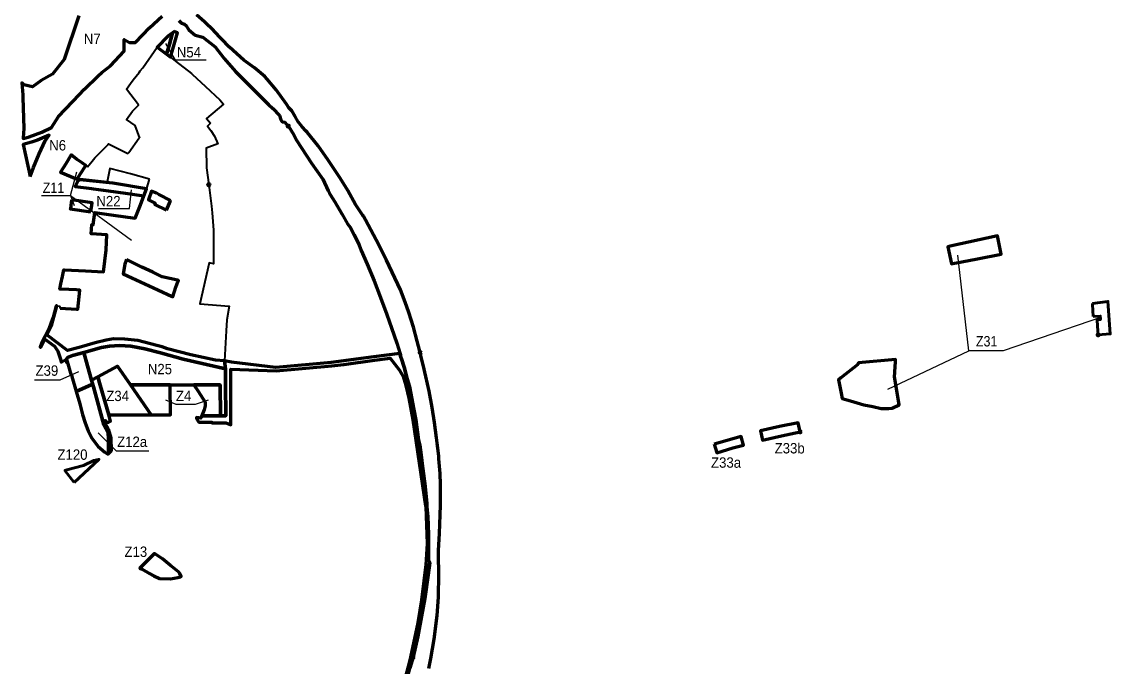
# Model space of a CAD drawing. Extents: x -650277 to -643422, y -1073980 to -1066720.
# Drawn here: x -645938 to -643422, y -1070696 to -1069207 of the extents above; entities that cross this region are included whole.
import ezdxf

# ---------------------------------------------------------------- set-up
doc = ezdxf.new("R2010")
doc.units = 0
doc.header["$LTSCALE"] = 9.6
doc.header["$PDMODE"] = 32
doc.header["$PDSIZE"] = 4.8
for name, color, linetype, lineweight in [('1', 7, 'Continuous', 60), ('11', 7, 'Continuous', 60), ('15', 7, 'Continuous', 60), ('3', 7, 'Continuous', 60), ('40', 7, 'Continuous', 60), ('42', 7, 'Continuous', 60), ('5', 7, 'Continuous', 60), ('60', 7, 'Continuous', 60), ('63', 7, 'Continuous', 25), ('7', 7, 'Continuous', 60), ('8', 7, 'Continuous', 60)]:
    doc.layers.add(name, color=color, linetype=linetype, lineweight=lineweight)

msp = doc.modelspace()

# ---------------------------------------------------------------- linework, layer by layer
at = {"layer": '1', "lineweight": 25}
msp.add_line((-645826, -1069608), (-645685, -1069711), dxfattribs=at)
at = {"layer": '1'}
msp.add_line((-645623.75, -1069825.97), (-645590.964, -1069841.09), dxfattribs=at)
at = {"layer": '1', "lineweight": 40}
msp.add_line((-645726.542, -1069939.398), (-645742.967, -1069941.862), dxfattribs=at)
for points in [[(-645668.722, -1069398.75), (-645696.19, -1069362.01), (-645692.38, -1069356.67), (-645690.81, -1069354.28), (-645687.22, -1069349), (-645680.8, -1069341.08), (-645667, -1069324.06), (-645664.89, -1069320.2), (-645658.9, -1069312.83), (-645625.11, -1069265.42), (-645604.114, -1069281.49), (-645594.94, -1069288.511)], [(-645594.94, -1069288.511), (-645583.13, -1069297.55), (-645546.19, -1069325.81), (-645544.26, -1069327.35), (-645513.41, -1069356.18), (-645480.72, -1069386.96), (-645471.738, -1069397.026), (-645511.464, -1069429.794), (-645501.878, -1069440.838)], [(-645665.58, -1069475.61), (-645675.91, -1069446.56), (-645696.45, -1069432.21), (-645682.28, -1069412.88), (-645678.06, -1069408.54), (-645668.61, -1069398.9), (-645668.722, -1069398.75)], [(-645501.878, -1069440.838), (-645508.994, -1069447.955), (-645501, -1069458), (-645493, -1069471), (-645484.783, -1069488.256), (-645512, -1069499), (-645511, -1069544), (-645506, -1069583)], [(-645786.388, -1069541.673), (-645779.376, -1069532.962), (-645778.754, -1069532.198), (-645769.369, -1069520.672), (-645768.995, -1069520.305), (-645752.715, -1069504.328), (-645738.986, -1069489.868), (-645737.897, -1069488.534), (-645702.82, -1069506.64), (-645692.87, -1069511.229), (-645690.84, -1069508.32), (-645667.31, -1069474.6), (-645665.58, -1069475.61)], [(-645836.44, -1069534.5), (-645824.05, -1069514.34), (-645811.75, -1069523.81), (-645808.1, -1069526.61), (-645799.07, -1069532.8), (-645790.62, -1069538.59), (-645786.388, -1069541.673)], [(-645810.08, -1069570.39), (-645848.78, -1069553.91), (-645836.44, -1069534.5)], [(-645643.16, -1069570.6), (-645687.29, -1069558.04), (-645734.5, -1069545.89), (-645736.8, -1069556.91), (-645741.14, -1069576.19), (-645769.04, -1069573), (-645803.513, -1069569.263), (-645810.08, -1069570.39)], [(-645676.34, -1069660.28), (-645670.23, -1069644.67), (-645664.19, -1069629.24), (-645657.52, -1069612.2), (-645656.15, -1069608.71), (-645649.91, -1069592.39), (-645648.68, -1069589.06), (-645644.56, -1069575.61), (-645643.16, -1069570.6)], [(-645506, -1069583), (-645500.137, -1069632.833), (-645500.137, -1069632.833)], [(-645500.137, -1069632.833), (-645498, -1069648), (-645495, -1069688), (-645495, -1069744), (-645495, -1069766), (-645504.976, -1069763.332), (-645527, -1069858), (-645459.312, -1069864.01), (-645464.288, -1069895.362), (-645465.756, -1069921.035), (-645469.701, -1069990.011)], [(-645839.721, -1069780.247), (-645839.658, -1069779.835), (-645791.2, -1069781.92), (-645749.48, -1069784.61), (-645743.36, -1069733.7), (-645743.01, -1069730.72), (-645741.43, -1069698.68), (-645763.24, -1069697.58), (-645777.62, -1069696.85), (-645776.45, -1069675.26), (-645773.02, -1069675.47), (-645769.36, -1069648), (-645769.264, -1069647.213), (-645726.57, -1069653.22), (-645676.34, -1069660.28)], [(-645804.185, -1069825.84), (-645804.28, -1069826.76), (-645812.18, -1069826.3), (-645847.62, -1069824.26), (-645850.63, -1069824.09), (-645848.35, -1069812.09), (-645844.57, -1069795.07), (-645841.41, -1069779.76), (-645839.658, -1069779.835), (-645839.721, -1069780.247)], [(-645742.967, -1069941.862), (-645768.424, -1069948.431), (-645833, -1069966), (-645880.431, -1069930.3), (-645874.219, -1069917.496), (-645869.262, -1069905.935), (-645863.95, -1069889.468), (-645857.289, -1069863.338), (-645857.204, -1069862.954), (-645850.92, -1069863.41), (-645849.79, -1069868.4), (-645808.84, -1069870.75), (-645808.28, -1069865.39), (-645804.185, -1069825.84)], [(-645469.701, -1069990.011), (-645490.814, -1069988.074), (-645547.4, -1069976.382), (-645614.072, -1069957.797), (-645625.979, -1069954.92), (-645670.325, -1069943.002), (-645699.889, -1069939.714), (-645726.542, -1069939.398)]]:
    msp.add_lwpolyline(points, dxfattribs=at)
at = {"layer": '1'}
for points in [[(-645836.44, -1069534.5), (-645848.78, -1069553.91), (-645810.08, -1069570.39), (-645803.07, -1069558.62), (-645790.62, -1069538.59), (-645799.07, -1069532.8), (-645808.1, -1069526.61), (-645811.75, -1069523.81), (-645824.05, -1069514.34)], [(-645639.638, -1070114.895), (-645594.733, -1070114.868), (-645595.2, -1070045.403), (-645687.31, -1070045.724)], [(-645522.587, -1070116.952), (-645478.664, -1070117.114), (-645479.429, -1070045.409), (-645540.433, -1070045.752), (-645530.3, -1070060.08), (-645514.49, -1070085.4), (-645514.56, -1070090.91), (-645514.61, -1070094.35), (-645517.02, -1070103.08), (-645518.35, -1070106.87), (-645521.73, -1070114.83)], [(-645594.769, -1070494.065), (-645577.47, -1070490.3), (-645571.13, -1070488.89), (-645569.97, -1070488.3), (-645572.86, -1070481.41), (-645575.7, -1070477.77), (-645591.49, -1070465.19), (-645594.62, -1070462.7), (-645612.77, -1070447.82), (-645631.63, -1070435.3), (-645636.42, -1070439.93), (-645648.9, -1070452.38), (-645665.6, -1070469.04), (-645660.29, -1070471.12), (-645643.4, -1070481.02), (-645633.35, -1070486.91), (-645620.22, -1070493)]]:
    msp.add_lwpolyline(points, close=True, dxfattribs=at)
at = {"layer": '1', "lineweight": 25}
for points in [[(-645893, -1069608), (-645826, -1069608), (-645811, -1069553)], [(-643442.122, -1069889.276), (-643669.749, -1069967.17), (-643749.085, -1069967.17)]]:
    msp.add_lwpolyline(points, dxfattribs=at)
at = {"layer": '1'}
for points in [[(-645849.79, -1069868.4), (-645811.848, -1069870.577), (-645808.84, -1069870.75), (-645804.28, -1069826.76), (-645812.18, -1069826.3), (-645847.62, -1069824.26), (-645850.63, -1069824.09), (-645848.35, -1069812.09), (-645844.57, -1069795.07), (-645841.41, -1069779.76), (-645839.658, -1069779.835), (-645791.2, -1069781.92), (-645749.48, -1069784.61), (-645743.36, -1069733.7), (-645741.43, -1069698.68), (-645777.62, -1069696.85), (-645776.45, -1069675.26), (-645773.02, -1069675.47), (-645769.264, -1069647.213), (-645726.57, -1069653.22), (-645676.34, -1069660.28), (-645664.19, -1069629.24), (-645656.15, -1069608.71)], [(-645594.58, -1069619.56), (-645621.56, -1069605.68), (-645626.95, -1069602.91), (-645638.203, -1069597.8), (-645645.715, -1069618.085), (-645629.78, -1069626.03), (-645630.93, -1069628.84), (-645603.7, -1069641.75)], [(-645823.082, -1069618.279), (-645823.13, -1069618.452), (-645825.295, -1069632.053), (-645826.133, -1069638.843), (-645826.151, -1069639.057), (-645778.45, -1069645.92)], [(-645778.45, -1069645.92), (-645775.46, -1069625.13), (-645823.082, -1069618.279)], [(-645603.7, -1069641.75), (-645594.818, -1069620.139), (-645594.58, -1069619.56)], [(-645696.517, -1069756.039), (-645700.028, -1069766.286), (-645704.355, -1069788.786), (-645623.75, -1069825.97)], [(-645578.134, -1069803.73), (-645613.84, -1069795.78), (-645635.79, -1069785.23), (-645660.57, -1069773.31), (-645696.517, -1069756.039)], [(-645590.964, -1069841.09), (-645589.23, -1069841.89), (-645582.31, -1069820.05), (-645577.52, -1069807.26), (-645576.34, -1069804.13), (-645578.134, -1069803.73)], [(-645772.853, -1070049.868), (-645774.423, -1070044.167), (-645783.063, -1070047.855), (-645812.76, -1070060.53)], [(-645812.76, -1070060.53), (-645804.52, -1070089.63), (-645797.66, -1070113.88), (-645791.72, -1070133.09), (-645784.83, -1070151.9), (-645784.83, -1070151.9)], [(-645737.756, -1070204.389), (-645737.624, -1070169.544), (-645738.79, -1070156.281), (-645748.62, -1070137.889), (-645772.853, -1070049.868)], [(-645784.83, -1070151.9), (-645776.26, -1070168.94), (-645761.78, -1070188.29), (-645746.73, -1070201.04), (-645739.12, -1070205.9), (-645737.756, -1070204.389)]]:
    msp.add_lwpolyline(points, dxfattribs=at)
at = {"layer": '1', "lineweight": 53}
for points in [[(-643450.3, -1069929.7), (-643422.204, -1069927.68), (-643427.6, -1069852.59), (-643463.51, -1069857.44)], [(-643463.51, -1069857.44), (-643463.31, -1069860.18), (-643461.327, -1069887.84)], [(-643461.327, -1069887.84), (-643445.37, -1069886.7), (-643444.79, -1069894.68), (-643452.77, -1069895.25), (-643451.74, -1069909.63), (-643450.3, -1069929.7)]]:
    msp.add_lwpolyline(points, dxfattribs=at)
msp.add_lwpolyline([(-645816.9, -1070270.96), (-645760.05, -1070217.79), (-645760.91, -1070217.98), (-645772.08, -1070220.39), (-645795.85, -1070231.81), (-645833.92, -1070241.96), (-645838.53, -1070243.19)], close=True, dxfattribs=at)
at = {"layer": '1'}
for p in [(-645506, -1069583), (-643450.3, -1069929.7)]:
    msp.add_point(p, dxfattribs=at)
at = {"layer": '11'}
msp.add_lwpolyline([(-645639.638, -1070114.895), (-645687.31, -1070045.724), (-645717.36, -1070002.12), (-645762.868, -1070026.606), (-645757.215, -1070045.97), (-645737.075, -1070114.955)], close=True, dxfattribs=at)
at = {"layer": '15'}
for points in [[(-645586.39, -1069229.32), (-645589.844, -1069231.908), (-645597.738, -1069261.522), (-645604.114, -1069281.49), (-645594.94, -1069288.511), (-645587.298, -1069264.578), (-645578.713, -1069232.375)], [(-645735.532, -1069956.306), (-645712.222, -1069954.725), (-645686.147, -1069956.306), (-645654.145, -1069962.232), (-645617.403, -1069971.714), (-645565.133, -1069986.508), (-645467.472, -1070008.38), (-645469.701, -1069990.011), (-645490.814, -1069988.074), (-645547.4, -1069976.382), (-645601.753, -1069962.317), (-645614.072, -1069957.797), (-645625.979, -1069954.92), (-645670.325, -1069943.002), (-645699.889, -1069939.714), (-645726.542, -1069939.398), (-645742.967, -1069941.862), (-645768.424, -1069948.431), (-645806, -1069959), (-645833, -1069966), (-645880.431, -1069930.3), (-645874.219, -1069917.496), (-645869.262, -1069905.935), (-645863.95, -1069889.468), (-645857.289, -1069863.338), (-645857.204, -1069862.954), (-645858.78, -1069862.84), (-645865.78, -1069888.76), (-645870.89, -1069903.5), (-645876.15, -1069916.47), (-645892.09, -1069947.98), (-645895.66, -1069958.42), (-645894.25, -1069958.7), (-645885.422, -1069940.184), (-645862.782, -1069955.809), (-645854.81, -1069967.927), (-645849.1, -1069986.42), (-645847.135, -1069993.337), (-645836.64, -1069987.18), (-645834.65, -1069994.21), (-645833.32, -1069991.86), (-645835, -1069985), (-645833, -1069982), (-645821, -1069978), (-645794.679, -1069970.596), (-645753.706, -1069959.071)]]:
    msp.add_lwpolyline(points, close=True, dxfattribs=at)
for points in [[(-645061.76, -1069981.21), (-645064.052, -1069973.429), (-645124.233, -1069980.695), (-645222.809, -1069993.701), (-645350.784, -1070005.227), (-645453.852, -1069992.968), (-645469.701, -1069990.011), (-645467.472, -1070008.38), (-645467.068, -1070044.959), (-645466.96, -1070117.157), (-645478.664, -1070117.114), (-645522.587, -1070116.952), (-645524.82, -1070122.48), (-645534.63, -1070121.09), (-645534.7, -1070122.95), (-645529.17, -1070131.4), (-645499.276, -1070131.652), (-645499.142, -1070133.293), (-645466.862, -1070133.219), (-645454.881, -1070137.836), (-645455.073, -1070009.111), (-645350.591, -1070013.242), (-645221.99, -1070001.66), (-645194.003, -1069998.417), (-645123.206, -1069988.629), (-645086.484, -1069984.195), (-645065.235, -1070011.695)], [(-645033.53, -1070674.55), (-645022.64, -1070626.93), (-645014.07, -1070580.72), (-645006.44, -1070538.78), (-644998.92, -1070484.58), (-644995.14, -1070455.72), (-644998.17, -1070450.59), (-644998.25, -1070430.5), (-644997.87, -1070391.16), (-644999.47, -1070349.63), (-645001.64, -1070326.4), (-645001.81, -1070324.58), (-645002.308, -1070319.268), (-645005.98, -1070280.14), (-645013.51, -1070222.04), (-645013.77, -1070220.04), (-645016.92, -1070196.32), (-645018.56, -1070184.92), (-645021.14, -1070173.07), (-645027.49, -1070126.56), (-645032.21, -1070102.73), (-645042.27, -1070049.23), (-645047.28, -1070031.83), (-645054.73, -1070004.56), (-645060.612, -1069985.022), (-645061.76, -1069981.21)], [(-645065.235, -1070011.695), (-645056.555, -1070026.163), (-645050.293, -1070047.035), (-645043.92, -1070076.344), (-645034.122, -1070126.616), (-645004.791, -1070324.889), (-645004.523, -1070326.697)], [(-645757.215, -1070045.97), (-645762.868, -1070026.606), (-645777.143, -1070034.287), (-645772.853, -1070049.868), (-645748.62, -1070137.889)], [(-645737.63, -1070147.39), (-645747.67, -1070129.14), (-645745.29, -1070127.83), (-645744.73, -1070129), (-645743.87, -1070130.15), (-645742.67, -1070131.07), (-645741.83, -1070131.53), (-645740.89, -1070131.8), (-645739.41, -1070131.93), (-645738.41, -1070131.78), (-645737.48, -1070131.45), (-645734.77, -1070130.18), (-645732.91, -1070129.5), (-645737.075, -1070114.955), (-645757.215, -1070045.97)], [(-645748.62, -1070137.889), (-645738.79, -1070156.281), (-645737.624, -1070169.544), (-645737.756, -1070204.389)], [(-645737.756, -1070204.389), (-645731.3, -1070197.24), (-645731.94, -1070167.87), (-645737.63, -1070147.39)], [(-645004.523, -1070326.697), (-645004.434, -1070327.302), (-645001.312, -1070412.099), (-645004.327, -1070461.264), (-645014.277, -1070543.11), (-645023.048, -1070595.033), (-645039.574, -1070675.065)], [(-645039.574, -1070675.065), (-645045.493, -1070696.321), (-645059.308, -1070747.712), (-645059.403, -1070749.195), (-645053.21, -1070749.75), (-645052.4, -1070746.427), (-645046.63, -1070722.77), (-645041, -1070700.44), (-645033.53, -1070674.55)]]:
    msp.add_lwpolyline(points, dxfattribs=at)
msp.add_point((-645033.53, -1070674.55), dxfattribs=at)
at = {"layer": '3'}
for points in [[(-643791.88, -1069725.25), (-643797.75, -1069726.51), (-643789.3, -1069766.05), (-643786.35, -1069765.46), (-643764.94, -1069761.27), (-643729.34, -1069754.3), (-643674.3, -1069743.53), (-643682.61, -1069701.16)], [(-643920.84, -1070026.46), (-643920.29, -1070017.73), (-643920.16, -1070015.69), (-643918.69, -1069992.23), (-643918.88, -1069986.82), (-644004.06, -1069994.59), (-644005.92, -1069998.62), (-644044.7, -1070029.04), (-644050.12, -1070033.64), (-644044.18, -1070064.43), (-644041.71, -1070077.29), (-644022.77, -1070082.66), (-643991.99, -1070091.37), (-643971.03, -1070095.79), (-643951.99, -1070100.35), (-643933.96, -1070100.18), (-643926.33, -1070099.5), (-643909.87, -1070091.95)]]:
    msp.add_lwpolyline(points, close=True, dxfattribs=at)
for points in [[(-645794.679, -1069970.596), (-645821, -1069978), (-645833, -1069982), (-645835, -1069985), (-645833.32, -1069991.86)], [(-645777.143, -1070034.287), (-645786.238, -1070001.251), (-645794.679, -1069970.596)], [(-645833.32, -1069991.86), (-645828.9, -1070007.76), (-645825.08, -1070021.52)], [(-645825.08, -1070021.52), (-645823.76, -1070021.67), (-645822.549, -1070025.948), (-645812.76, -1070060.53), (-645783.063, -1070047.855), (-645774.423, -1070044.167), (-645777.143, -1070034.287)]]:
    msp.add_lwpolyline(points, dxfattribs=at)
at = {"layer": '40'}
for points in [[(-645698.83, -1069602.85), (-645656.15, -1069608.71), (-645649.91, -1069592.39), (-645727.71, -1069579.61), (-645803.33, -1069571.62), (-645808.18, -1069573.7), (-645814.82, -1069586.81), (-645777.26, -1069592.07), (-645772.58, -1069592.73), (-645738.13, -1069597.46)], [(-645595.2, -1070045.403), (-645479.429, -1070045.409), (-645478.664, -1070117.114), (-645466.96, -1070117.157), (-645467.068, -1070044.959), (-645467.472, -1070008.38), (-645565.133, -1069986.508), (-645617.403, -1069971.714), (-645654.145, -1069962.232), (-645686.147, -1069956.306), (-645712.222, -1069954.725), (-645735.532, -1069956.306), (-645753.706, -1069959.071), (-645794.679, -1069970.596), (-645786.238, -1070001.251), (-645777.143, -1070034.287), (-645762.868, -1070026.606), (-645717.36, -1070002.12), (-645687.31, -1070045.724)]]:
    msp.add_lwpolyline(points, close=True, dxfattribs=at)
at = {"layer": '42'}
msp.add_lwpolyline([(-645604.114, -1069281.49), (-645597.738, -1069261.522), (-645589.844, -1069231.908), (-645600.55, -1069239.93), (-645625.11, -1069265.42)], close=True, dxfattribs=at)
at = {"layer": '5'}
msp.add_lwpolyline([(-644338.06, -1070182.64), (-644331.9, -1070202.4), (-644295.01, -1070190.9), (-644269.84, -1070184.57), (-644275.05, -1070164.59)], close=True, dxfattribs=at)
at = {"layer": '60'}
for points in [[(-645575.58, -1069203.57), (-645568.9, -1069209.87), (-645567.07, -1069210.45), (-645562.17, -1069212.02), (-645560.72, -1069214.25), (-645559.33, -1069214.54), (-645552.2, -1069225.59), (-645537.44, -1069237.41), (-645519.59, -1069242.38), (-645491.63, -1069264.25), (-645470.44, -1069291.24), (-645444.62, -1069321.35), (-645405.7, -1069360.27), (-645368.13, -1069397.37), (-645358.04, -1069406.84), (-645342.49, -1069423.06), (-645339.31, -1069433.27), (-645336.66, -1069437.47), (-645330.57, -1069438.89), (-645327.2, -1069442.53), (-645323.36, -1069445.79), (-645322.13, -1069447.96)], [(-645017.46, -1069970.61), (-645018.28, -1069967.49), (-645024.45, -1069944.43), (-645032.85, -1069912.07), (-645043.5, -1069878.37), (-645051.78, -1069854.2), (-645063.26, -1069825.99), (-645095.1, -1069757.62), (-645118.98, -1069710.08), (-645143.56, -1069664.05), (-645148.8, -1069656.1), (-645150.3, -1069653.84), (-645153.33, -1069649.24), (-645166.67, -1069629), (-645184.88, -1069596.58), (-645202.56, -1069568.23), (-645230.1, -1069525.98), (-645253.4, -1069493.06), (-645278.31, -1069461.33), (-645281.4, -1069458.4), (-645290.5, -1069449.03), (-645299.61, -1069437.97), (-645306.16, -1069425.55), (-645314.14, -1069412.54), (-645321.1, -1069405.21), (-645326.59, -1069396.64), (-645350.63, -1069363.98), (-645371.12, -1069339.47), (-645376.38, -1069332.65), (-645400.07, -1069313.32), (-645424.8, -1069295.24), (-645458.45, -1069265.56), (-645494.13, -1069227.63), (-645515.89, -1069206.66), (-645534.25, -1069190.56)], [(-645322.13, -1069447.96), (-645309.62, -1069467.79), (-645303.57, -1069480.49), (-645268.57, -1069533.23), (-645242.75, -1069570.26), (-645230.42, -1069597.39), (-645227.27, -1069602.68), (-645225.7, -1069605.32), (-645214.76, -1069622.37), (-645198.41, -1069650.49), (-645185.17, -1069673.38), (-645179.12, -1069681.3), (-645170.3, -1069698.91), (-645158.43, -1069722.61), (-645153.44, -1069734.71), (-645140.27, -1069766.68), (-645123.84, -1069805.38), (-645108.74, -1069843.58), (-645094.42, -1069882.65), (-645083.31, -1069913.37), (-645071.53, -1069948.89), (-645063.96, -1069973.73), (-645063.23, -1069976.2), (-645062.57, -1069978.46)], [(-645062.57, -1069978.46), (-645061.76, -1069981.21), (-645060.612, -1069985.022), (-645054.73, -1070004.56), (-645047.28, -1070031.83), (-645042.27, -1070049.23), (-645032.21, -1070102.73), (-645027.49, -1070126.56), (-645021.14, -1070173.07), (-645018.56, -1070184.92), (-645016.92, -1070196.32), (-645013.77, -1070220.04), (-645013.51, -1070222.04), (-645005.98, -1070280.14), (-645002.308, -1070319.268), (-645001.81, -1070324.58), (-645001.64, -1070326.4), (-644999.47, -1070349.63), (-644997.87, -1070391.16), (-644998.25, -1070430.5), (-644998.17, -1070450.59), (-644995.14, -1070455.72), (-644998.92, -1070484.58), (-645006.44, -1070538.78), (-645014.07, -1070580.72), (-645022.64, -1070626.93), (-645033.53, -1070674.55)], [(-644996.88, -1070059.73), (-645004.02, -1070026.44), (-645010.54, -1069999.3), (-645015.548, -1069978.177), (-645016.01, -1069976.23), (-645016.89, -1069972.82), (-645017.46, -1069970.61)], [(-644997.14, -1070700.88), (-644992.6, -1070677.92), (-644985.04, -1070633.43), (-644978.44, -1070578.56), (-644975.05, -1070536.16), (-644974.44, -1070482.48), (-644975.29, -1070440.14), (-644974.69, -1070427.86), (-644972.48, -1070389.15), (-644971.37, -1070345.98), (-644970.61, -1070323.44), (-644970.55, -1070321.56), (-644970.524, -1070315.358), (-644970.36, -1070275.49), (-644971.47, -1070250.14), (-644974, -1070216.2), (-644974.29, -1070213.17), (-644974.49, -1070210.98), (-644976.94, -1070191.41), (-644978.49, -1070180.05), (-644979.57, -1070167.9), (-644984.21, -1070132.81), (-644989.62, -1070097.79), (-644996.88, -1070059.73)], [(-645033.53, -1070674.55), (-645041, -1070700.44)]]:
    msp.add_lwpolyline(points, dxfattribs=at)
for p in [(-645322.13, -1069447.96), (-645017.46, -1069970.61), (-645033.53, -1070674.55)]:
    msp.add_point(p, dxfattribs=at)
at = {"layer": '63'}
for p, q in [((-645826, -1069608), (-645817, -1069631)), ((-643749.085, -1069967.17), (-643774.294, -1069746.101)), ((-643936.672, -1070055.449), (-643749.085, -1069967.17))]:
    msp.add_line(p, q, dxfattribs=at)
for points in [[(-645512, -1069295), (-645583, -1069295), (-645605, -1069257)], [(-645761, -1069638), (-645689, -1069638), (-645685, -1069595)], [(-645909, -1070034), (-645850, -1070034), (-645806.657, -1070014.297)], [(-645606, -1070080), (-645582, -1070090), (-645537, -1070090), (-645507, -1070080)], [(-645762, -1070156), (-645720, -1070198), (-645645, -1070198)]]:
    msp.add_lwpolyline(points, dxfattribs=at)
at = {"layer": '7'}
msp.add_line((-645918.82, -1069563.81), (-645910.9, -1069543.64), dxfattribs=at)
for points in [[(-645806.806, -1069193.112), (-645840.644, -1069294.052), (-645867.026, -1069327.317), (-645893.291, -1069341.938), (-645913.23, -1069356.892), (-645933.792, -1069352.53), (-645938.399, -1069347.452), (-645936.046, -1069375.651), (-645935.58, -1069381.24), (-645933.97, -1069453.52), (-645934.8, -1069474.71), (-645935.05, -1069476.32), (-645928.99, -1069474.55), (-645921.13, -1069472.25), (-645892.03, -1069461.43), (-645869.91, -1069451.02), (-645853.28, -1069425.27), (-645838.17, -1069409.28), (-645819.62, -1069389.66), (-645793.63, -1069362.15), (-645761.411, -1069331.17), (-645753.58, -1069323.64), (-645733.1, -1069308.58), (-645701.62, -1069274.36), (-645701.33, -1069247.86), (-645689, -1069254.5), (-645675.82, -1069254.48), (-645643.34, -1069220.59), (-645613.9, -1069193.45)], [(-645910.9, -1069543.64), (-645897.92, -1069511.49), (-645884.01, -1069481.56), (-645875.02, -1069468.52), (-645902.19, -1069480.13), (-645916.13, -1069484.55), (-645934.97, -1069490.31), (-645918.82, -1069563.81)]]:
    msp.add_lwpolyline(points, dxfattribs=at)
at = {"layer": '8'}
for p, q in [((-644138.78, -1070154.07), (-644143.31, -1070132.95)), ((-644182.31, -1070163.66), (-644138.78, -1070154.07))]:
    msp.add_line(p, q, dxfattribs=at)
msp.add_lwpolyline([(-644143.31, -1070132.95), (-644143.31, -1070132.95), (-644143.31, -1070132.95), (-644187.11, -1070141.58), (-644230.4, -1070152.08), (-644226.23, -1070173.28), (-644182.31, -1070163.66)], dxfattribs=at)
msp.add_point((-644138.78, -1070154.07), dxfattribs=at)

# ---------------------------------------------------------------- texts
at = {"layer": '1'}
for s, width, p in [('Z11', 0.9, (-645890, -1069602)), ('Z31', 0.9, (-643732.773, -1069956.784)), ('Z120', 0.95, (-645855.898, -1070218.668))]:
    msp.add_text(s, height=24, dxfattribs=dict(at, width=width)).set_placement(p)
at = {"layer": '63', "width": 0.95}
for s, p in [('N7', (-645795, -1069258)), ('N54', (-645580, -1069289)), ('N6', (-645875, -1069504)), ('N22', (-645766, -1069633)), ('Z39', (-645906.58, -1070024.53)), ('N25', (-645647, -1070021)), ('Z34', (-645743, -1070083)), ('Z4', (-645582, -1070083)), ('Z12a', (-645718, -1070189)), ('Z33b', (-644198, -1070204)), ('Z33a', (-644345, -1070237)), ('Z13', (-645701, -1070443))]:
    msp.add_text(s, height=24, dxfattribs=at).set_placement(p)

doc.saveas('drawing.dxf')
